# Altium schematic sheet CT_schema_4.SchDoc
size 520 x 457 mm
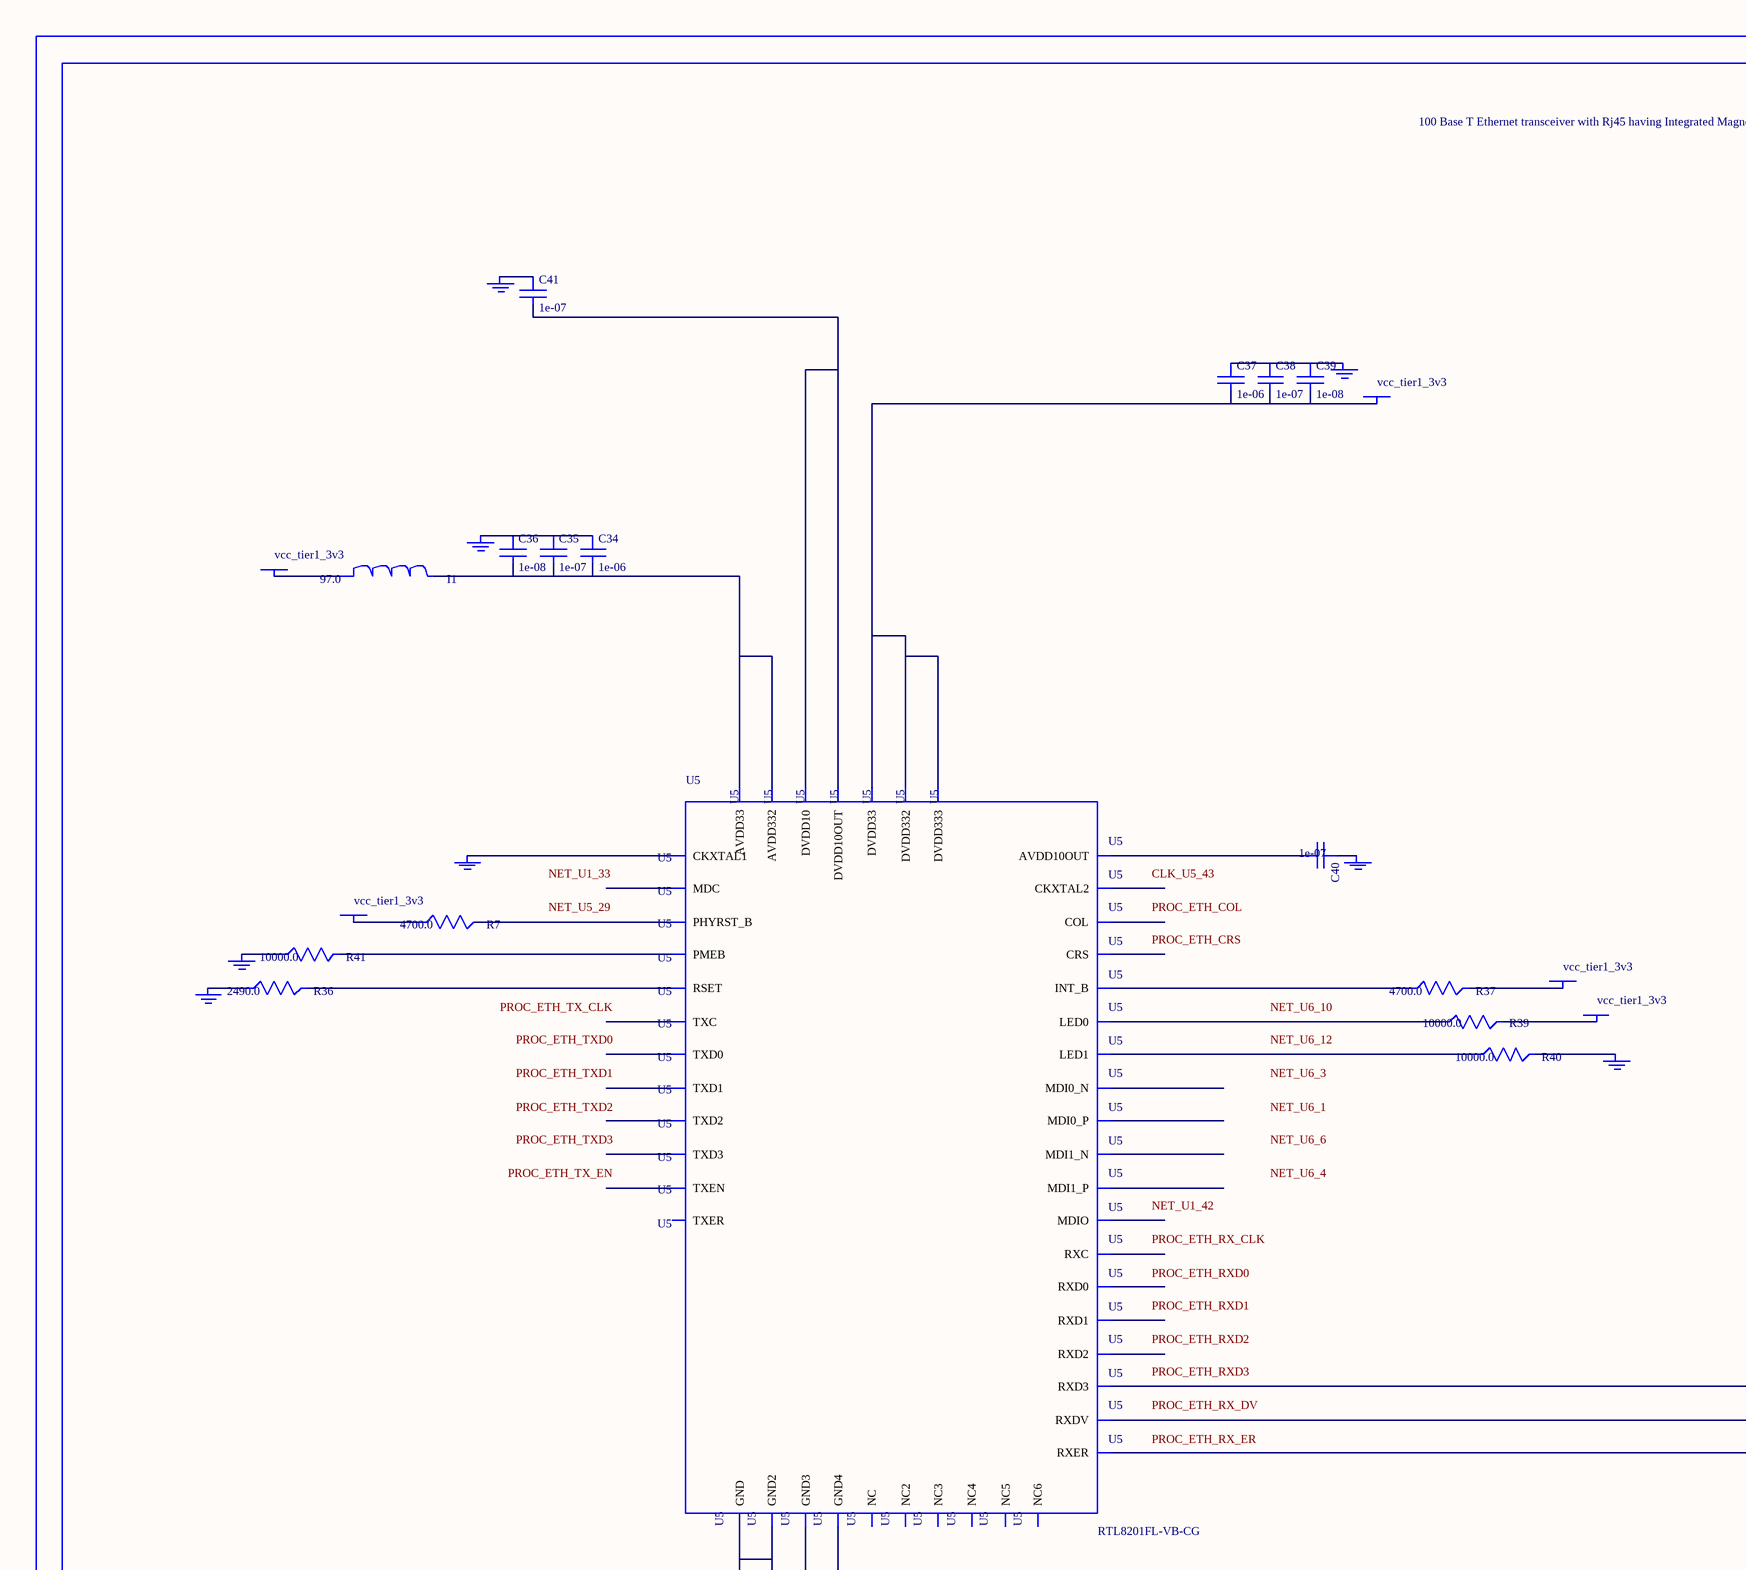
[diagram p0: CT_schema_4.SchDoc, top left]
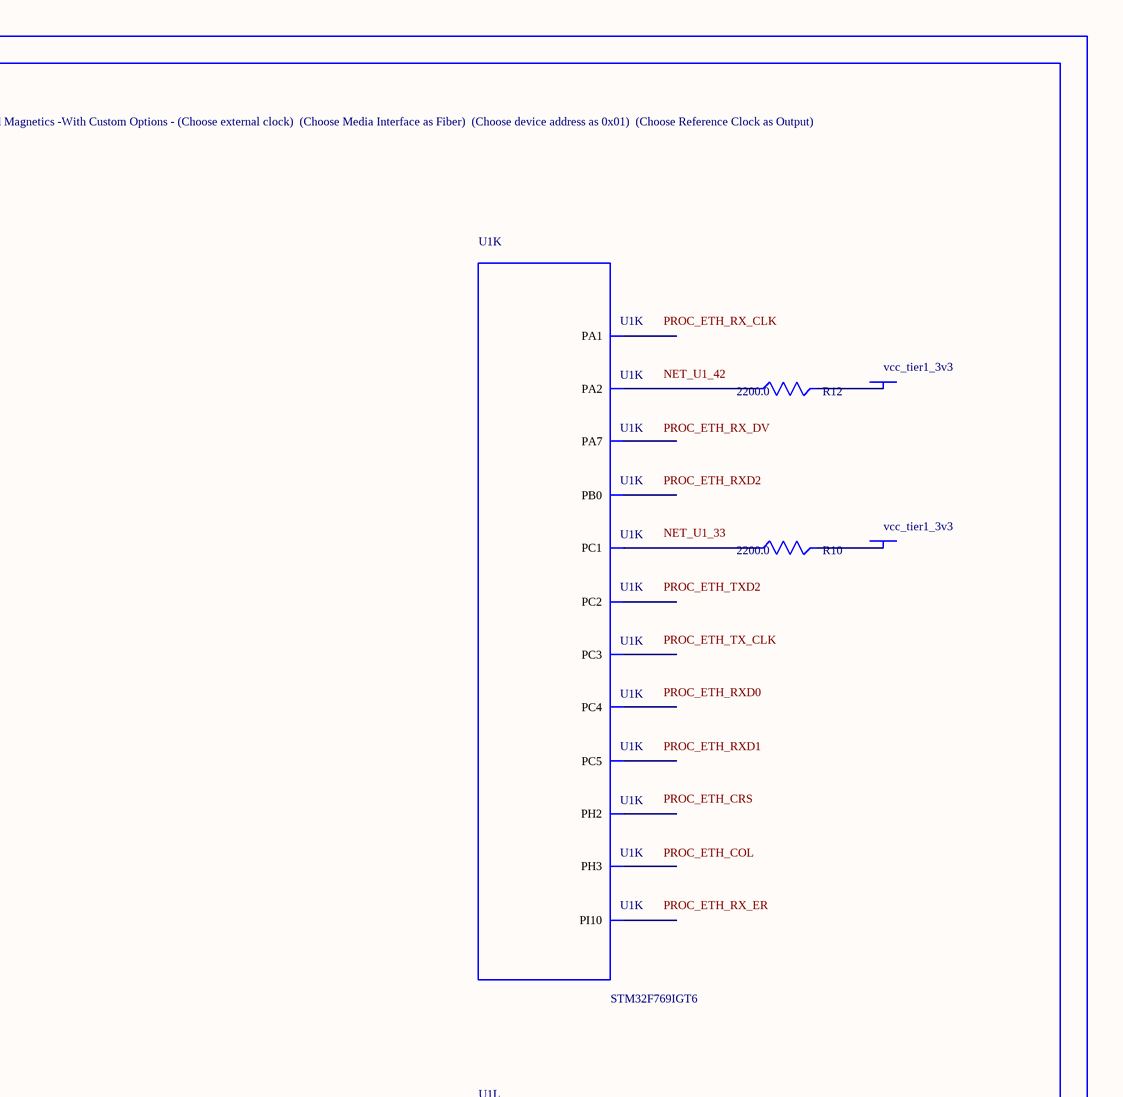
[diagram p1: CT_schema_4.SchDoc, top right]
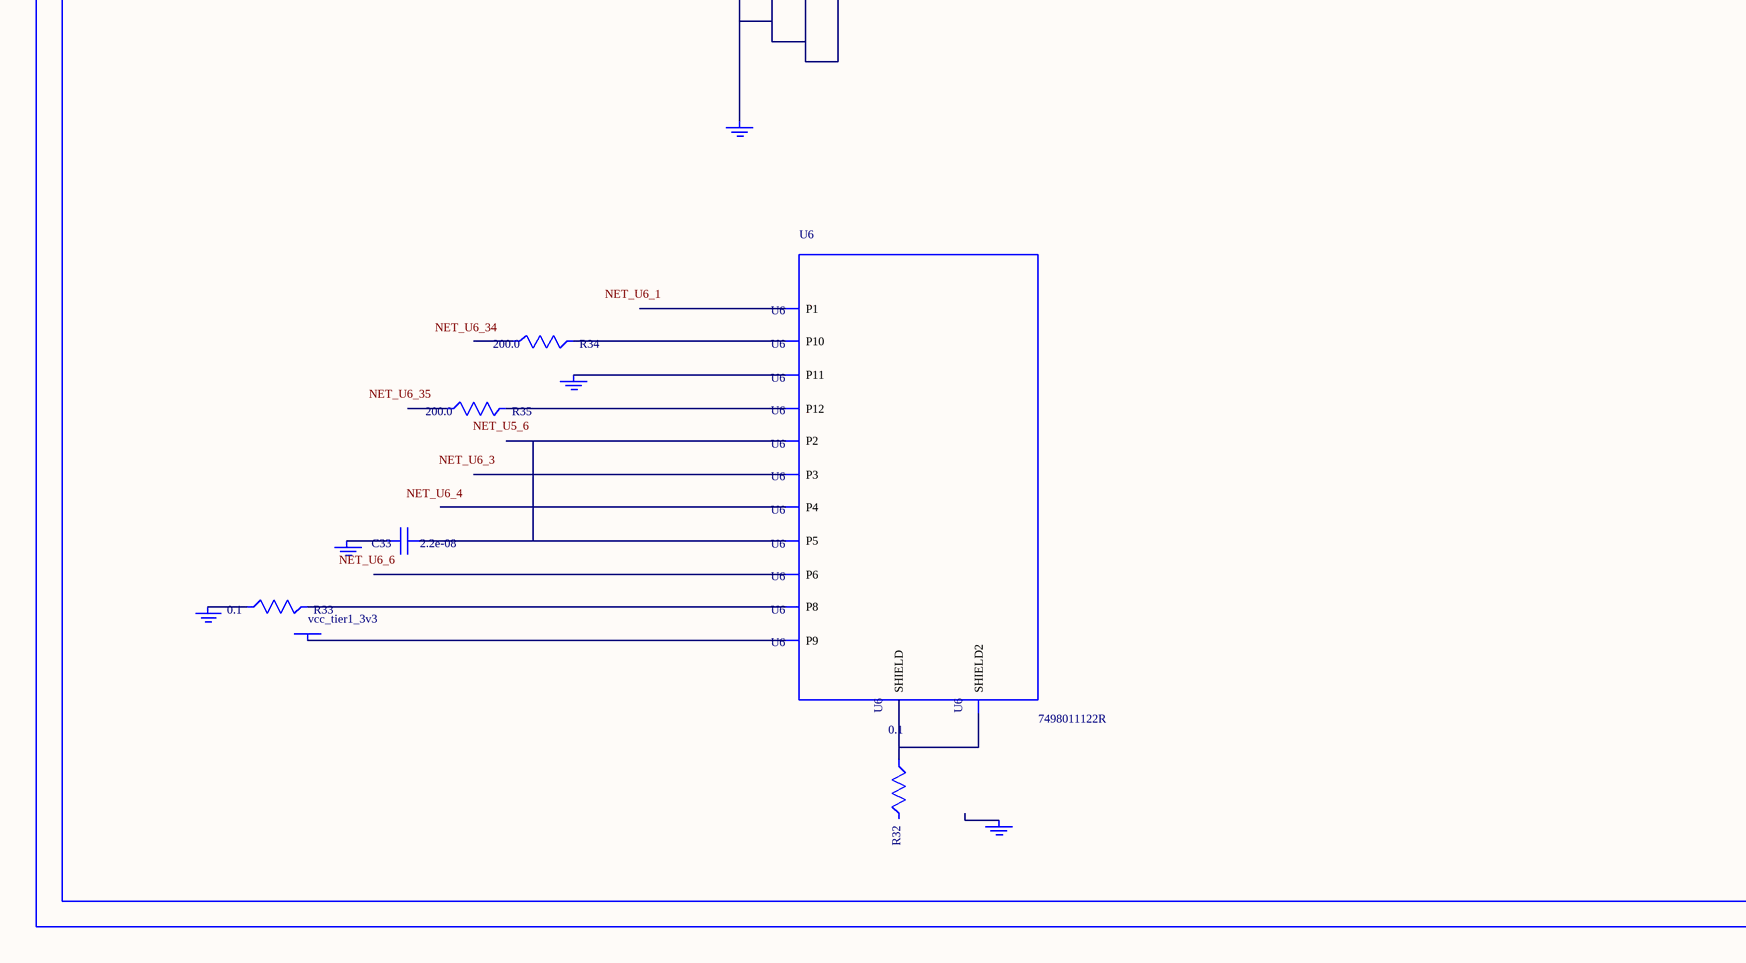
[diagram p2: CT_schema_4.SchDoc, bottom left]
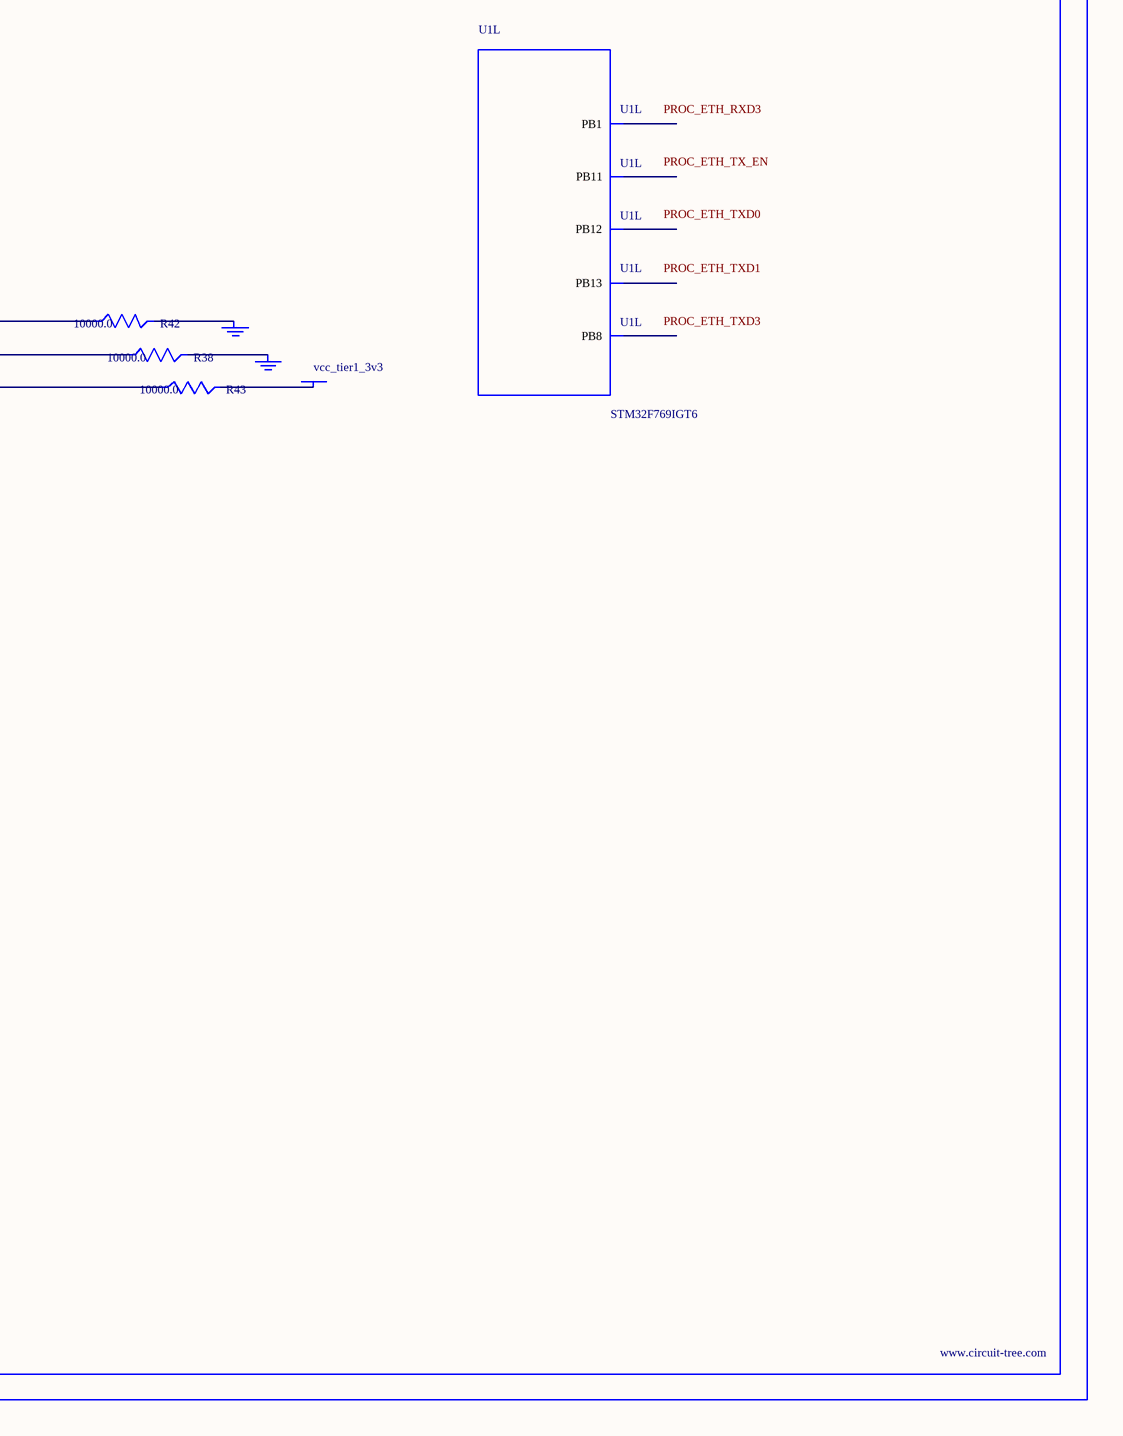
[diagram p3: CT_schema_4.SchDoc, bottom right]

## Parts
BORDER3  (no value)
C33  2.2e-08  [C0402]
C34  1e-06  [C0603]
C35  1e-07  [C0402]
C36  1e-08  [C0402]
C37  1e-06  [C0603]
C38  1e-07  [C0402]
C39  1e-08  [C0402]
C40  1e-07  [C0402]
C41  1e-07  [C0402]
GND_INSTANCE_3_0  (no value)
GND_INSTANCE_3_1  (no value)
GND_INSTANCE_3_2  (no value)
GND_INSTANCE_3_3  (no value)
GND_INSTANCE_3_4  (no value)
GND_INSTANCE_3_5  (no value)
GND_INSTANCE_3_6  (no value)
GND_INSTANCE_3_7  (no value)
GND_INSTANCE_3_8  (no value)
GND_INSTANCE_3_9  (no value)
GND_INSTANCE_3_10  (no value)
GND_INSTANCE_3_11  (no value)
GND_INSTANCE_3_12  (no value)
GND_INSTANCE_3_13  (no value)
GND_INSTANCE_3_14  (no value)
I1  97.0  [R0603]
POWER_INSTANCE_3_0  vcc_tier1_3v3
POWER_INSTANCE_3_1  vcc_tier1_3v3
POWER_INSTANCE_3_2  vcc_tier1_3v3
POWER_INSTANCE_3_3  vcc_tier1_3v3
POWER_INSTANCE_3_4  vcc_tier1_3v3
POWER_INSTANCE_3_5  vcc_tier1_3v3
POWER_INSTANCE_3_6  vcc_tier1_3v3
POWER_INSTANCE_3_7  vcc_tier1_3v3
POWER_INSTANCE_3_8  vcc_tier1_3v3
R7  4700.0  [R0603]
R10  2200.0  [R0603]
R12  2200.0  [R0603]
R32  0.1  [R0603]
R33  0.1  [R0603]
R34  200.0  [R0603]
R35  200.0  [R0603]
R36  2490.0  [R0603]
R37  4700.0  [R0603]
R38  10000.0  [R0603]
R39  10000.0  [R0603]
R40  10000.0  [R0603]
R41  10000.0  [R0603]
R42  10000.0  [R0603]
R43  10000.0  [R0603]
U1  STM32F769IGT6  [LQFP176]  (parts K,L of 13)
U5  RTL8201FL-VB-CG  [RTL8201FL-VB-CG]
U6  7498011122R  [7498011122R]

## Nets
NetC33_1: C33.1 U6.2(P2) U6.5(P5)
NetC33_2: C33.2 GND_INSTANCE_3_11.0(GND)
NetC34_1: C34.1 C35.1 C36.1 GND_INSTANCE_3_0.0(GND)
NetC34_2: C34.2 C35.2 C36.2 I1.2 U5.6(AVDD33) U5.41(AVDD332)
NetC37_1: C37.1 C38.1 C39.1 GND_INSTANCE_3_3.0(GND)
NetC37_2: C37.2 C38.2 C39.2 POWER_INSTANCE_3_1.0(PWR) U5.15(DVDD33) U5.21(DVDD332) U5.37(DVDD333)
NetC40_1: C40.1 GND_INSTANCE_3_9.0(GND)
NetC40_2: C40.2 U5.48(AVDD10OUT)
NetC41_1: C41.1 GND_INSTANCE_3_6.0(GND)
NetC41_2: C41.2 U5.28(DVDD10) U5.40(DVDD10OUT)
NetGND_INSTANCE_3_1_0: GND_INSTANCE_3_1.0(GND) R41.1
NetGND_INSTANCE_3_2_0: GND_INSTANCE_3_2.0(GND) R38.2
NetGND_INSTANCE_3_4_0: GND_INSTANCE_3_4.0(GND) R42.2
NetGND_INSTANCE_3_5_0: GND_INSTANCE_3_5.0(GND) R40.2
NetGND_INSTANCE_3_7_0: GND_INSTANCE_3_7.0(GND) U5.42(CKXTAL1)
NetGND_INSTANCE_3_8_0: GND_INSTANCE_3_8.0(GND) R36.1
NetGND_INSTANCE_3_10_0: GND_INSTANCE_3_10.0(GND) U5.7(GND) U5.20(GND2) U5.33(GND3) U5.47(GND4)
NetGND_INSTANCE_3_12_0: GND_INSTANCE_3_12.0(GND) R33.1
NetGND_INSTANCE_3_13_0: GND_INSTANCE_3_13.0(GND) U6.11(P11)
NetI1_1: I1.1 POWER_INSTANCE_3_0.0(PWR)
NetPOWER_INSTANCE_3_2_0: POWER_INSTANCE_3_2.0(PWR) R37.2
NetPOWER_INSTANCE_3_3_0: POWER_INSTANCE_3_3.0(PWR) R39.2
NetPOWER_INSTANCE_3_4_0: POWER_INSTANCE_3_4.0(PWR) R43.2
NetPOWER_INSTANCE_3_5_0: POWER_INSTANCE_3_5.0(PWR) R7.1
NetPOWER_INSTANCE_3_6_0: POWER_INSTANCE_3_6.0(PWR) R10.2
NetPOWER_INSTANCE_3_7_0: POWER_INSTANCE_3_7.0(PWR) R12.2
NetPOWER_INSTANCE_3_8_0: POWER_INSTANCE_3_8.0(PWR) U6.9(P9)
NetR7_2: R7.2 U5.29(PHYRST_B)
NetR10_1: R10.1 U1.33(PC1)
NetR12_1: R12.1 U1.42(PA2)
NetR32_1: R32.1 U6.13(SHIELD) U6.14(SHIELD2)
NetR33_2: R33.2 U6.8(P8)
NetR34_2: R34.2 U6.10(P10)
NetR35_2: R35.2 U6.12(P12)
NetR36_2: R36.2 U5.46(RSET)
NetR37_1: R37.1 U5.32(INT_B)
NetR38_1: R38.1 U5.13(RXDV)
NetR39_1: R39.1 U5.34(LED0)
NetR40_1: R40.1 U5.35(LED1)
NetR41_2: R41.2 U5.10(PMEB)
NetR42_1: R42.1 U5.18(RXD3)
NetR43_1: R43.1 U5.39(RXER)

Not connected (* = marked no-connect by the designer): GND_INSTANCE_3_14 0(GND); R32 2; R34 1; R35 1; U1 12(PI10) 34(PC2) 35(PC3) 41(PA1) 43(PH2) 44(PH3) 53(PA7) 54(PC4) 55(PC5) 56(PB0) 57(PB1) 80(PB11) 85(PB12) 86(PB13) 167(PB8); U5 1(MDI0_P) 2(MDI0_N) 3(NC) 4(MDI1_P) 5(MDI1_N) 8(NC2) 9(NC3) 11(NC4) 12(TXER) 14(RXD0) 16(RXD1) 17(RXD2) 19(RXC) 22(TXC) 23(TXD0) 24(TXD1) 25(TXD2) 26(TXD3) 27(TXEN) 30(MDC) 31(MDIO) 36(CRS) 38(COL) 43(CKXTAL2) 44(NC5) 45(NC6); U6 1(P1) 3(P3) 4(P4) 6(P6)

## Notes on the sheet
- Labels drawn without touching a wire or pin: CLK_U5_43, NET_U1_33, NET_U1_42, NET_U5_6, NET_U5_29, NET_U6_1, NET_U6_3, NET_U6_4, NET_U6_6, NET_U6_10, NET_U6_12, NET_U6_34, NET_U6_35, PROC_ETH_COL, PROC_ETH_CRS, PROC_ETH_RX_CLK, PROC_ETH_RX_DV, PROC_ETH_RX_ER, PROC_ETH_RXD0, PROC_ETH_RXD1, PROC_ETH_RXD2, PROC_ETH_RXD3, PROC_ETH_TX_CLK, PROC_ETH_TX_EN, PROC_ETH_TXD0, PROC_ETH_TXD1, PROC_ETH_TXD2, PROC_ETH_TXD3

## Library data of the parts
BORDER3 = BORDER_PAGE3
C33 = C0402C223K3RAC
C34 C37 = C0603C105K3RACTU
C35 C38 C40 C41 = C0402C104K3RACTU
C36 C39 = C0402C103K3RAC
GND_INSTANCE_3_0-GND_INSTANCE_3_14 = GND
I1 = I1
POWER_INSTANCE_3_0-POWER_INSTANCE_3_8 = PWR
R7 R37 = RC0603JR-074K7L
R10 R12 = RC0603JR-072K2L
R32 R33 = ERJ-3RSFR10V
R34 R35 = RC0603JR-07200RL
R36 = ERA-3AED2490V
R38-R43 = RC0603JR-0710KL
